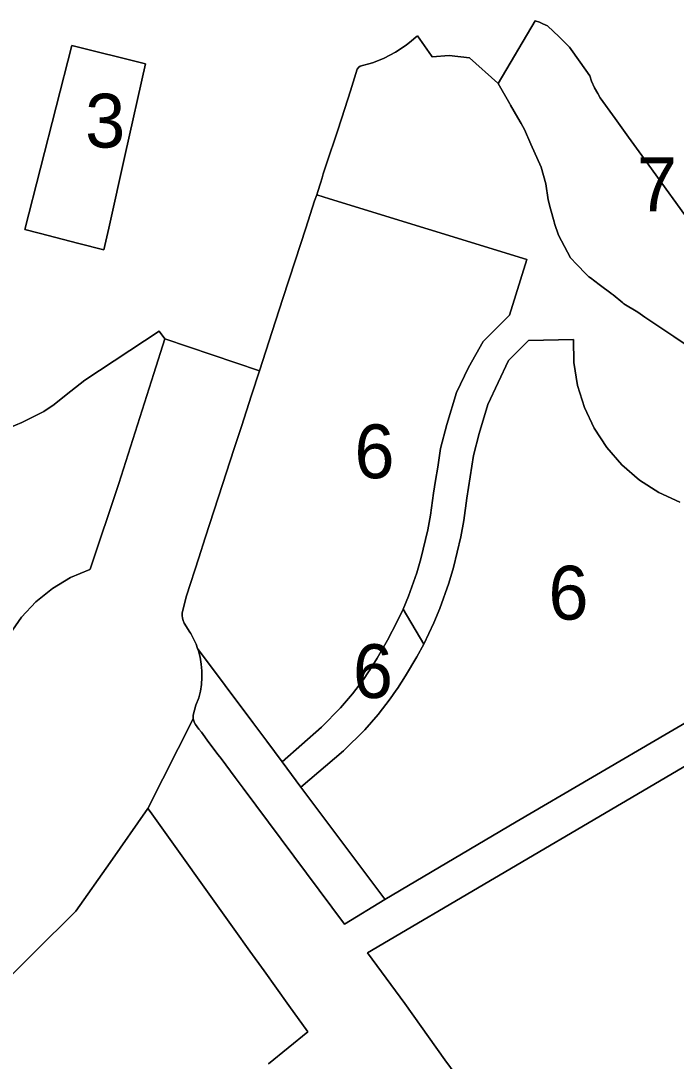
# Model space of a CAD drawing. Extents: x 598968 to 613553, y 4409678 to 4430833.
# Drawn here: x 608676.3 to 608822.4, y 4415419.2 to 4415651.3 of the extents above; entities that cross this region are included whole.
import ezdxf

# ---------------------------------------------------------------- set-up
doc = ezdxf.new("R2010")
doc.units = 0
for name, color, linetype in [('1', 7, 'Continuous'), ("ZONA 3. ILLES  D'EDIFICIS ENTRE MITGERES. EIXAMPLE.", 7, 'Continuous'), ('ZONA 6. EDIFICIS DE PISOS_ AÏLLATS I EN PARCEL.LES', 7, 'Continuous'), ('ZONA 7. CONJUNTS AMB ORDENACIONS ESPECÍFIQUES', 7, 'Continuous')]:
    doc.layers.add(name, color=color, linetype=linetype)

msp = doc.modelspace()

# ---------------------------------------------------------------- linework, layer by layer
at = {"layer": '1'}
for points in [[(608669.4293, 4415558.6903), (608676.5303, 4415561.6955), (608681.425, 4415564.1663), (608683.6992, 4415565.7104), (608686.4391, 4415567.9005), (608690.5491, 4415571.1605), (608707.1039, 4415582.0806), (608708.3988, 4415580.3307), (608729.4828, 4415573.2435), (608730.8883, 4415577.5695), (608732.3074, 4415581.9696), (608734.7005, 4415589.3318), (608737.4272, 4415597.7495), (608739.7879, 4415605.0499), (608741.7833, 4415611.1214), (608742.2405, 4415612.5103), (608742.4771, 4415613.2296), (608743.0519, 4415615.0443), (608743.4436, 4415616.2807), (608743.7067, 4415617.1232), (608744.3371, 4415619.1496), (608746.947, 4415626.8995), (608748.5034, 4415631.7498), (608749.747, 4415635.6895), (608751.277, 4415640.5094), (608751.6369, 4415640.9294), (608751.9467, 4415641.1493), (608754.6769, 4415641.9094), (608756.3969, 4415642.5894), (608757.3069, 4415642.9594), (608759.8168, 4415644.2594), (608762.1768, 4415645.8295), (608763.3968, 4415646.8195), (608764.3668, 4415647.6295), (608764.6259, 4415647.8832), (608764.7196, 4415647.975), (608767.79, 4415643.4645), (608767.9567, 4415643.2196), (608771.7467, 4415643.5597), (608776.3166, 4415642.9997), (608782.6027, 4415637.3859), (608782.6766, 4415637.32), (608790.9364, 4415651.2899), (608791.9264, 4415650.9599), (608792.6364, 4415650.6499), (608793.6864, 4415650.18), (608796.2664, 4415647.7101), (608798.5964, 4415645.4001), (608800.9764, 4415642.0302), (608803.1063, 4415639.0003), (608803.5063, 4415637.8203), (608804.1463, 4415636.3603), (608804.8663, 4415635.0804), (608805.4063, 4415634.1204), (608808.7263, 4415629.5105), (608811.7442, 4415625.3271), (608815.2564, 4415620.4542), (608827.0861, 4415604.0412)], [(608824.1363, 4415579.2815), (608821.8002, 4415580.8576), (608819.3872, 4415582.4856), (608815.3656, 4415585.199), (608813.7764, 4415586.2712), (608810.7164, 4415588.1812), (608810.47, 4415588.3856), (608808.3162, 4415590.1353), (608808.2403, 4415590.1969), (608808.0865, 4415590.3118), (608808.084, 4415590.3136), (608805.1569, 4415592.5015), (608803.2298, 4415593.9419), (608802.8565, 4415594.2209), (608802.3003, 4415594.7976), (608800.2447, 4415596.9294), (608798.8065, 4415598.4208), (608796.0965, 4415603.5007), (608795.2383, 4415606.111), (608795.2274, 4415606.1447), (608795.1365, 4415606.4206), (608794.3695, 4415609.3231), (608794.3685, 4415609.327), (608793.8365, 4415611.3406), (608793.2865, 4415614.9105), (608792.2665, 4415618.6104), (608789.9753, 4415623.792), (608788.53, 4415627.0612), (608787.8166, 4415628.3683), (608787.0799, 4415629.6522), (608785.463, 4415632.47), (608785.2965, 4415632.7599), (608782.6766, 4415637.32), (608782.6027, 4415637.3859), (608776.3166, 4415642.9997), (608771.7467, 4415643.5597), (608767.9567, 4415643.2196), (608767.79, 4415643.4645), (608764.7196, 4415647.975), (608764.6259, 4415647.8832), (608764.3668, 4415647.6295), (608763.3968, 4415646.8195), (608762.1768, 4415645.8295), (608759.8168, 4415644.2594), (608757.3069, 4415642.9594), (608756.3969, 4415642.5894), (608754.6769, 4415641.9094), (608751.9467, 4415641.1493), (608751.6369, 4415640.9294), (608751.277, 4415640.5094), (608749.747, 4415635.6895), (608748.5034, 4415631.7498), (608746.947, 4415626.8995), (608744.3371, 4415619.1496), (608743.7067, 4415617.1232), (608743.4436, 4415616.2807), (608743.0519, 4415615.0443), (608742.4771, 4415613.2296), (608742.2405, 4415612.5103), (608745.1271, 4415611.6196), (608789.0678, 4415598.0865), (608785.2409, 4415585.6627), (608779.3458, 4415579.7867), (608776.0401, 4415573.9739), (608773.3814, 4415568.3894), (608771.213, 4415561.2311), (608769.8417, 4415555.8631), (608769.2079, 4415551.7574), (608768.7425, 4415548.7418), (608768.307, 4415545.9208), (608767.6271, 4415541.0009), (608767.0271, 4415537.7509), (608765.4771, 4415531.321), (608764.5371, 4415528.151), (608762.7072, 4415522.941), (608761.4772, 4415520.091), (608761.4755, 4415520.0869), (608766.0898, 4415512.2354), (608768.3204, 4415517.0202), (608769.6967, 4415520.2093), (608771.6749, 4415525.8409), (608772.7227, 4415529.375), (608774.3656, 4415536.1904), (608775.0332, 4415539.8062), (608775.7283, 4415544.8355), (608777.1983, 4415554.3595), (608778.4387, 4415559.2148), (608780.3958, 4415565.6758), (608784.9602, 4415575.4994), (608789.4637, 4415579.9883), (608799.4616, 4415580.1856), (608799.5617, 4415575.0454), (608800.3768, 4415569.9693), (608801.8913, 4415565.0563), (608804.0755, 4415560.4022), (608806.8867, 4415556.0978), (608810.2703, 4415552.2271), (608814.1602, 4415548.8655), (608818.4804, 4415546.0786), (608823.1469, 4415543.9209)], [(608673.7894, 4415514.3809), (608676.4743, 4415518.2487), (608679.6748, 4415521.702), (608683.3276, 4415524.6728), (608687.3607, 4415527.1023), (608691.6945, 4415528.9426), (608691.7292, 4415528.991), (608698.1241, 4415548.0959), (608705.9489, 4415572.6608), (608708.3988, 4415580.3307), (608707.1039, 4415582.0806), (608690.5491, 4415571.1605), (608686.4391, 4415567.9005), (608683.6992, 4415565.7104), (608681.425, 4415564.1663), (608676.5303, 4415561.6955), (608669.4293, 4415558.6903)], [(608669.6657, 4415434.0606), (608688.5653, 4415452.7408), (608696.25, 4415463.5808), (608704.6147, 4415475.6008), (608714.7278, 4415495.6305), (608714.7178, 4415496.4505), (608715.3278, 4415498.6405), (608715.9378, 4415500.2904), (608716.3078, 4415501.7704), (608716.5478, 4415503.2704), (608716.6678, 4415504.7904), (608716.6578, 4415506.3104), (608716.5278, 4415507.8304), (608716.2578, 4415509.3303), (608715.8678, 4415510.8003), (608715.685, 4415511.313), (608715.3578, 4415512.2302), (608714.7278, 4415513.6102), (608714.1578, 4415514.6301), (608713.9878, 4415514.9401), (608712.6678, 4415516.9501), (608712.4478, 4415517.5001), (608712.2978, 4415518.0701), (608712.2378, 4415518.6501), (608712.2478, 4415519.24), (608713.2078, 4415523.03), (608715.9577, 4415531.53), (608717.3971, 4415536.0003), (608720.34, 4415545.1119), (608723.8501, 4415555.8682), (608725.4575, 4415560.8298), (608727.7174, 4415567.8097), (608729.4828, 4415573.2435), (608708.3988, 4415580.3307), (608705.9489, 4415572.6608), (608698.1241, 4415548.0959), (608691.7292, 4415528.991), (608691.6945, 4415528.9426), (608687.3607, 4415527.1023), (608683.3276, 4415524.6728), (608679.6748, 4415521.702), (608676.4743, 4415518.2487), (608673.7894, 4415514.3809)], [(608828.7064, 4415497.2324), (608820.6866, 4415492.5224), (608786.697, 4415472.592), (608757.4583, 4415455.2892), (608748.4376, 4415449.8217), (608725.8477, 4415480.1109), (608724.0778, 4415482.4908), (608720.9178, 4415486.7207), (608720.2647, 4415487.5976), (608718.2291, 4415490.3308), (608716.5356, 4415492.6047), (608716.0002, 4415493.3234), (608715.2278, 4415494.3605), (608714.9578, 4415494.8405), (608714.9318, 4415494.9297), (608714.7278, 4415495.6305), (608704.6147, 4415475.6008), (608705.0967, 4415474.9267), (608723.8769, 4415448.6625), (608727.3657, 4415443.7833), (608730.5105, 4415439.3852), (608736.0136, 4415431.6891), (608740.2557, 4415425.7564), (608731.5124, 4415418.6742)], [(608885.0576, 4415413.9588), (608882.8293, 4415419.2443), (608859.1528, 4415473.2184), (608858.2634, 4415475.246), (608848.6362, 4415497.1929), (608848.4587, 4415497.1122), (608846.8762, 4415496.3929), (608841.9763, 4415494.2428), (608838.4463, 4415493.3628), (608753.5675, 4415443.4219), (608761.8975, 4415432.1322), (608770.7774, 4415419.542), (608778.3673, 4415409.2728)], [(608778.3673, 4415409.2728), (608770.7774, 4415419.542), (608761.8975, 4415432.1322), (608753.5675, 4415443.4219), (608838.4463, 4415493.3628)], [(608731.5124, 4415418.6742), (608740.2557, 4415425.7564), (608736.0136, 4415431.6891), (608730.5105, 4415439.3852), (608727.3657, 4415443.7833), (608723.8769, 4415448.6625), (608705.0967, 4415474.9267), (608704.6147, 4415475.6008), (608696.25, 4415463.5808), (608688.5653, 4415452.7408), (608669.6657, 4415434.0606)]]:
    msp.add_lwpolyline(points, dxfattribs=at)
for points in [[(608680.3879, 4415603.9485), (608677.1816, 4415604.7798), (608687.6977, 4415645.8181), (608704.0975, 4415641.7285), (608699.5476, 4415621.4886), (608695.8977, 4415605.0688), (608694.815, 4415600.2192), (608689.2578, 4415601.6487)], [(608766.0898, 4415512.2354), (608761.4755, 4415520.0869), (608760.1672, 4415517.281), (608758.0273, 4415513.1511), (608755.6973, 4415509.1211), (608753.9773, 4415506.4111), (608753.7773, 4415506.0911), (608752.6373, 4415504.4111), (608750.1974, 4415501.1611), (608747.5774, 4415498.0611), (608743.3075, 4415493.721), (608734.5439, 4415486.0205), (608738.7417, 4415480.3907), (608748.2347, 4415488.4969), (608752.935, 4415493.1407), (608755.9048, 4415496.5553), (608758.6165, 4415500.0625), (608759.9515, 4415501.9712), (608760.2142, 4415502.3785), (608762.0383, 4415505.1646), (608764.5821, 4415509.424)], [(608734.5439, 4415486.0205), (608731.1338, 4415490.5938), (608728.0076, 4415494.7866), (608715.685, 4415511.313), (608715.8678, 4415510.8003), (608716.2578, 4415509.3303), (608716.5278, 4415507.8304), (608716.6578, 4415506.3104), (608716.6678, 4415504.7904), (608716.5478, 4415503.2704), (608716.3078, 4415501.7704), (608715.9378, 4415500.2904), (608715.3278, 4415498.6405), (608714.7178, 4415496.4505), (608714.7278, 4415495.6305), (608714.9318, 4415494.9297), (608714.9578, 4415494.8405), (608715.2278, 4415494.3605), (608716.0002, 4415493.3234), (608716.5356, 4415492.6047), (608718.2291, 4415490.3308), (608720.2647, 4415487.5976), (608720.9178, 4415486.7207), (608724.0778, 4415482.4908), (608725.8477, 4415480.1109), (608748.4376, 4415449.8217), (608757.4583, 4415455.2892), (608757.4002, 4415455.3672), (608738.7417, 4415480.3907)]]:
    msp.add_lwpolyline(points, close=True, dxfattribs=at)
at = {"layer": "ZONA 3. ILLES  D'EDIFICIS ENTRE MITGERES. EIXAMPLE."}
msp.add_lwpolyline([(608695.8977, 4415605.0688), (608699.5476, 4415621.4886), (608704.0975, 4415641.7285), (608687.6977, 4415645.8181), (608677.1816, 4415604.7798), (608680.3879, 4415603.9485), (608689.2578, 4415601.6487), (608694.815, 4415600.2192)], close=True, dxfattribs=at)
at = {"layer": 'ZONA 6. EDIFICIS DE PISOS_ AÏLLATS I EN PARCEL.LES'}
for points in [[(608761.4755, 4415520.0869), (608761.4772, 4415520.091), (608762.7072, 4415522.941), (608764.5371, 4415528.151), (608765.4771, 4415531.321), (608767.0271, 4415537.7509), (608767.6271, 4415541.0009), (608768.307, 4415545.9208), (608768.7425, 4415548.7418), (608769.2079, 4415551.7574), (608769.8417, 4415555.8631), (608771.213, 4415561.2311), (608773.3814, 4415568.3894), (608776.0401, 4415573.9739), (608779.3458, 4415579.7867), (608785.2409, 4415585.6627), (608789.0678, 4415598.0865), (608745.1271, 4415611.6196), (608742.2405, 4415612.5103), (608741.7833, 4415611.1214), (608739.7879, 4415605.0499), (608737.4272, 4415597.7495), (608734.7005, 4415589.3318), (608732.3074, 4415581.9696), (608730.8883, 4415577.5695), (608729.4828, 4415573.2435), (608727.7174, 4415567.8097), (608725.4575, 4415560.8298), (608723.8501, 4415555.8682), (608720.34, 4415545.1119), (608717.3971, 4415536.0003), (608715.9577, 4415531.53), (608713.2078, 4415523.03), (608712.2478, 4415519.24), (608712.2378, 4415518.6501), (608712.2978, 4415518.0701), (608712.4478, 4415517.5001), (608712.6678, 4415516.9501), (608713.9878, 4415514.9401), (608714.1578, 4415514.6301), (608714.7278, 4415513.6102), (608715.3578, 4415512.2302), (608715.685, 4415511.313), (608728.0076, 4415494.7866), (608731.1338, 4415490.5938), (608734.5439, 4415486.0205), (608743.3075, 4415493.721), (608747.5774, 4415498.0611), (608750.1974, 4415501.1611), (608752.6373, 4415504.4111), (608753.7773, 4415506.0911), (608753.9773, 4415506.4111), (608755.6973, 4415509.1211), (608758.0273, 4415513.1511), (608760.1672, 4415517.281)], [(608766.0898, 4415512.2354), (608761.4755, 4415520.0869), (608760.1672, 4415517.281), (608758.0273, 4415513.1511), (608755.6973, 4415509.1211), (608753.9773, 4415506.4111), (608753.7773, 4415506.0911), (608752.6373, 4415504.4111), (608750.1974, 4415501.1611), (608747.5774, 4415498.0611), (608743.3075, 4415493.721), (608734.5439, 4415486.0205), (608738.7417, 4415480.3907), (608748.2347, 4415488.4969), (608752.935, 4415493.1407), (608755.9048, 4415496.5553), (608758.6165, 4415500.0625), (608759.9515, 4415501.9712), (608760.2142, 4415502.3785), (608762.0383, 4415505.1646), (608764.5821, 4415509.424)]]:
    msp.add_lwpolyline(points, close=True, dxfattribs=at)
msp.add_lwpolyline([(608823.1469, 4415543.9209), (608818.4804, 4415546.0786), (608814.1602, 4415548.8655), (608810.2703, 4415552.2271), (608806.8867, 4415556.0978), (608804.0755, 4415560.4022), (608801.8913, 4415565.0563), (608800.3768, 4415569.9693), (608799.5617, 4415575.0454), (608799.4616, 4415580.1856), (608789.4637, 4415579.9883), (608784.9602, 4415575.4994), (608780.3958, 4415565.6758), (608778.4387, 4415559.2148), (608777.1983, 4415554.3595), (608775.7283, 4415544.8355), (608775.0332, 4415539.8062), (608774.3656, 4415536.1904), (608772.7227, 4415529.375), (608771.6749, 4415525.8409), (608769.6967, 4415520.2093), (608768.3204, 4415517.0202), (608766.0898, 4415512.2354), (608764.5821, 4415509.424), (608762.0383, 4415505.1646), (608760.2142, 4415502.3785), (608759.9515, 4415501.9712), (608758.6165, 4415500.0625), (608755.9048, 4415496.5553), (608752.935, 4415493.1407), (608748.2347, 4415488.4969), (608738.7417, 4415480.3907), (608757.4002, 4415455.3672), (608757.4583, 4415455.2892), (608786.697, 4415472.592), (608820.6866, 4415492.5224), (608828.7064, 4415497.2324)], dxfattribs=at)
at = {"layer": 'ZONA 7. CONJUNTS AMB ORDENACIONS ESPECÍFIQUES'}
msp.add_lwpolyline([(608827.0861, 4415604.0412), (608815.2564, 4415620.4542), (608811.7442, 4415625.3271), (608808.7263, 4415629.5105), (608805.4063, 4415634.1204), (608804.8663, 4415635.0804), (608804.1463, 4415636.3603), (608803.5063, 4415637.8203), (608803.1063, 4415639.0003), (608800.9764, 4415642.0302), (608798.5964, 4415645.4001), (608796.2664, 4415647.7101), (608793.6864, 4415650.18), (608792.6364, 4415650.6499), (608791.9264, 4415650.9599), (608790.9364, 4415651.2899), (608782.6766, 4415637.32), (608785.2965, 4415632.7599), (608785.463, 4415632.47), (608787.0799, 4415629.6522), (608787.8166, 4415628.3683), (608788.53, 4415627.0612), (608789.9753, 4415623.792), (608792.2665, 4415618.6104), (608793.2865, 4415614.9105), (608793.8365, 4415611.3406), (608794.3685, 4415609.327), (608794.3695, 4415609.3231), (608795.1365, 4415606.4206), (608795.2274, 4415606.1447), (608795.2383, 4415606.111), (608796.0965, 4415603.5007), (608798.8065, 4415598.4208), (608800.2447, 4415596.9294), (608802.3003, 4415594.7976), (608802.8565, 4415594.2209), (608803.2298, 4415593.9419), (608805.1569, 4415592.5015), (608808.084, 4415590.3136), (608808.0865, 4415590.3118), (608808.2403, 4415590.1969), (608808.3162, 4415590.1353), (608810.47, 4415588.3856), (608810.7164, 4415588.1812), (608813.7764, 4415586.2712), (608815.3656, 4415585.199), (608819.3872, 4415582.4856), (608821.8002, 4415580.8576), (608824.1363, 4415579.2815)], dxfattribs=at)

# ---------------------------------------------------------------- texts
at = {"layer": "ZONA 3. ILLES  D'EDIFICIS ENTRE MITGERES. EIXAMPLE."}
msp.add_text('3', height=12, dxfattribs=at).set_placement((608690.6395, 4415623.0186))
at = {"layer": 'ZONA 6. EDIFICIS DE PISOS_ AÏLLATS I EN PARCEL.LES'}
for p in [(608750.6528, 4415549.2654), (608793.8889, 4415517.7374), (608750.3169, 4415500.2388)]:
    msp.add_text('6', height=12, dxfattribs=at).set_placement(p)
at = {"layer": 'ZONA 7. CONJUNTS AMB ORDENACIONS ESPECÍFIQUES'}
msp.add_text('7', height=12, dxfattribs=at).set_placement((608813.6213, 4415608.8079))

doc.saveas('drawing.dxf')
